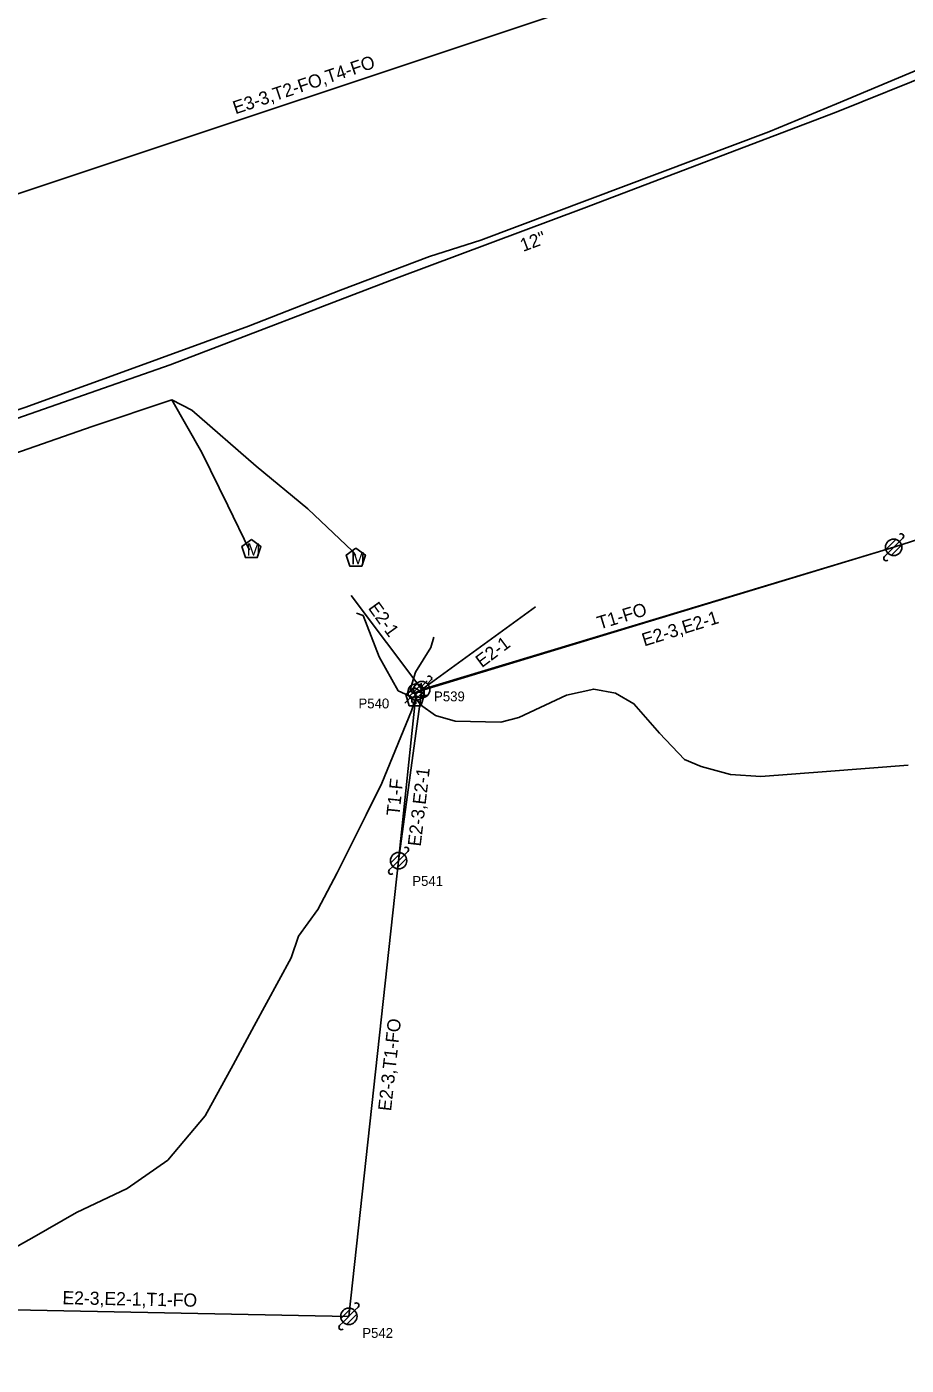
# Model space of a CAD drawing. Extents: x 1614474 to 1865144, y 1098877 to 1212550.
# Drawn here: x 1813359.1 to 1813627, y 1189614.1 to 1190021.4 of the extents above; entities that cross this region are included whole.
import ezdxf

# ---------------------------------------------------------------- set-up
doc = ezdxf.new("R2010")
doc.units = 0
for name, color, linetype in [('RD_EX_SU_H2O', 7, 'Continuous'), ('RD_EX_SU_Ovhd', 7, 'Continuous'), ('RD_EX_SU_Pole', 7, 'Continuous'), ('RD_EX_SU_Telecom', 7, 'Continuous'), ('RD_EX_SU_TX_H2O', 7, 'Continuous'), ('RD_EX_SU_TX_Pole', 7, 'Continuous')]:
    doc.layers.add(name, color=color, linetype=linetype)

# ---------------------------------------------------------------- blocks, each defined once
blk = doc.blocks.new('SUE_TPP')
at = {"layer": 'RD_EX_SU_Telecom'}
blk.add_lwpolyline([(0, 3), (-2.85, 0.93), (-1.76, -2.43), (1.76, -2.43), (2.85, 0.93)], close=True, dxfattribs=at)
blk.add_text('T', height=3.75, dxfattribs=at).set_placement((-1.25, -1.88))
blk = doc.blocks.new('SUE_WM')
at = {"layer": 'RD_EX_SU_H2O'}
blk.add_lwpolyline([(0, 3.05), (-2.9, 0.94), (-1.79, -2.47), (1.79, -2.47), (2.9, 0.94)], close=True, dxfattribs=at)
blk.add_text('M', height=3.75, dxfattribs=at).set_placement((-1.43, -1.88))
blk = doc.blocks.new('SUE_PTP')
at = {"layer": 'RD_EX_SU_Pole'}
for p, q in [((-2.48, -0.33), (0.33, 2.48)), ((-2.1, -1.36), (1.36, 2.1)), ((-1.4, -2.08), (2.08, 1.4)), ((-0.38, -2.47), (2.47, 0.38)), ((1.77, 1.77), (3.42, 3.42)), ((-3.42, -3.42), (-1.77, -1.77)), ((1.52, -1.99), (1.99, -1.52))]:
    blk.add_line(p, q, dxfattribs=at)
blk.add_circle((0, 0), 2.5, dxfattribs=at)

msp = doc.modelspace()

# ---------------------------------------------------------------- linework, layer by layer
at = {"layer": 'RD_EX_SU_H2O'}
for points in [[(1813049.93, 1189785.18), (1813062.98, 1189793.04), (1813077.41, 1189801.91), (1813100.8, 1189813.52), (1813124.24, 1189823.21), (1813173.48, 1189839.48), (1813207.95, 1189850.5), (1813242.12, 1189860.74), (1813307.93, 1189883.34), (1813347.93, 1189899.33), (1813402.79, 1189918.54), (1813471.7, 1189944.89), (1813528.83, 1189966.2), (1813605.69, 1189995.43), (1813667.12, 1190020.2)], [(1813076.17, 1189776.71), (1813070.48, 1189788.22), (1813083.19, 1189794.03), (1813114.42, 1189806.57), (1813134.39, 1189813.94), (1813156.92, 1189822.09), (1813179.27, 1189830.15), (1813208.26, 1189840.49), (1813244.46, 1189853.13), (1813287.8, 1189867.84), (1813318.33, 1189878.33), (1813350.77, 1189889.9), (1813379.04, 1189899.78), (1813403.28, 1189907.87), (1813412.45, 1189891.9), (1813420.34, 1189875.71), (1813427, 1189862.13)], [(1813403.28, 1189907.87), (1813409.4, 1189904.72), (1813429.03, 1189887.68), (1813444.72, 1189874.7), (1813458.39, 1189861.86), (1813459.22, 1189860.46)]]:
    msp.add_lwpolyline(points, dxfattribs=at)
at = {"layer": 'RD_EX_SU_Ovhd'}
for p, q in [((1813319.93, 1189958.41), (1813557.25, 1190037.52)), ((1813623.17, 1189863), (1813729.49, 1189897.64)), ((1813623.17, 1189863), (1813726.98, 1189897)), ((1813477.7, 1189818.95), (1813623.17, 1189863)), ((1813479.42, 1189819.69), (1813623.17, 1189863)), ((1813457.89, 1189848.34), (1813479.42, 1189819.69)), ((1813479.42, 1189819.69), (1813514.05, 1189844.91)), ((1813472.38, 1189767.62), (1813479.42, 1189819.69)), ((1813472.38, 1189767.62), (1813477.7, 1189818.95)), ((1813457.23, 1189628.94), (1813472.38, 1189767.62)), ((1813313.8, 1189631.73), (1813457.23, 1189628.94))]:
    msp.add_line(p, q, dxfattribs=at)
at = {"layer": 'RD_EX_SU_Pole'}
for p, q in [((1813620.76, 1189862.36), (1813623.82, 1189865.42)), ((1813621.41, 1189861.24), (1813624.94, 1189864.77)), ((1813622.53, 1189860.59), (1813625.59, 1189863.65)), ((1813624.94, 1189864.77), (1813626, 1189865.83)), ((1813620.34, 1189860.18), (1813621.41, 1189861.24)), ((1813481.18, 1189821.46), (1813482.24, 1189822.52)), ((1813476.59, 1189816.86), (1813477.65, 1189817.92)), ((1813469.97, 1189766.97), (1813473.03, 1189770.04)), ((1813470.62, 1189765.85), (1813474.15, 1189769.39)), ((1813474.15, 1189769.39), (1813475.21, 1189770.45)), ((1813469.56, 1189764.79), (1813470.62, 1189765.85)), ((1813471.74, 1189765.21), (1813474.8, 1189768.27)), ((1813454.81, 1189628.29), (1813457.88, 1189631.35)), ((1813455.46, 1189627.17), (1813459, 1189630.71)), ((1813459, 1189630.71), (1813460.06, 1189631.77)), ((1813454.4, 1189626.11), (1813455.46, 1189627.17)), ((1813456.58, 1189626.52), (1813459.64, 1189629.59))]:
    msp.add_line(p, q, dxfattribs=at)
for centre in [(1813623.17, 1189863), (1813479.42, 1189819.69), (1813472.38, 1189767.62), (1813457.23, 1189628.94)]:
    msp.add_circle(centre, 2.5, dxfattribs=at)
for centre, start, end in [((1813625.47, 1189866.36), 315, 135), ((1813620.88, 1189859.64), 135, 315), ((1813481.71, 1189823.05), 315, 135), ((1813477.12, 1189816.33), 135, 315), ((1813474.68, 1189770.98), 315, 135), ((1813470.09, 1189764.26), 135, 315), ((1813459.53, 1189632.3), 315, 135), ((1813454.93, 1189625.58), 135, 315)]:
    msp.add_arc(centre, 0.75, start, end, dxfattribs=at)
at = {"layer": 'RD_EX_SU_Telecom'}
for points in [[(1813481.84, 1189951.54), (1813497.41, 1189956.53), (1813585.12, 1189989.42), (1813605.76, 1189998.02), (1813630.95, 1190008.57)], [(1812986.98, 1189763.67), (1813005.44, 1189771.75), (1813024.19, 1189779.33), (1813053.31, 1189794.14), (1813073.59, 1189804.15), (1813101.03, 1189816.06), (1813126.47, 1189826.28), (1813144.04, 1189832.67), (1813167.98, 1189840.52), (1813203.88, 1189852.88), (1813226.05, 1189860.24), (1813250.43, 1189868.52), (1813290.34, 1189882.36), (1813332.67, 1189897.04), (1813358.52, 1189905.57), (1813386.31, 1189915.56), (1813426.66, 1189930.34), (1813454.68, 1189941.28), (1813481.84, 1189951.54)], [(1813459.57, 1189842.94), (1813461.58, 1189842.22), (1813466.47, 1189829.65), (1813472.27, 1189819.33), (1813476.93, 1189817.17)], [(1813476.97, 1189818.43), (1813475.95, 1189819.6), (1813477.55, 1189825.01), (1813482.2, 1189832.47), (1813483.12, 1189835.62)], [(1813477.62, 1189817.11), (1813479.05, 1189815.03), (1813483.64, 1189811.8), (1813489.65, 1189810.12), (1813503.52, 1189809.81), (1813509.02, 1189811.22), (1813523.55, 1189817.96), (1813531.82, 1189819.83), (1813538.49, 1189818.65), (1813544.05, 1189815.39), (1813551.84, 1189806.41), (1813559.42, 1189798.39), (1813564.52, 1189796.34), (1813573.51, 1189793.88), (1813582.72, 1189793.29), (1813602.71, 1189794.8), (1813627.54, 1189796.74)], [(1813255.57, 1189614.06), (1813263.68, 1189617.82), (1813281.32, 1189622.74), (1813302.06, 1189628.54), (1813321.29, 1189634.79), (1813337.62, 1189640.37), (1813352.54, 1189648.16), (1813361.42, 1189653.14), (1813374.32, 1189660.59), (1813389.71, 1189667.88), (1813402.08, 1189676.45), (1813413.44, 1189689.97), (1813422.05, 1189705.47), (1813428.42, 1189717.32), (1813439.68, 1189738.07), (1813441.87, 1189744.68), (1813447.8, 1189752.78), (1813453.72, 1189763.94), (1813462.54, 1189781.61), (1813467.31, 1189791.17), (1813476.35, 1189813.22), (1813477.46, 1189816.76)]]:
    msp.add_lwpolyline(points, dxfattribs=at)

# ---------------------------------------------------------------- block references
at = {"layer": 'RD_EX_SU_H2O'}
for p in [(1813427.54, 1189862.35), (1813459.36, 1189859.7)]:
    msp.add_blockref('SUE_WM', p, dxfattribs=at)
at = {"layer": 'RD_EX_SU_Telecom'}
for name, p in [('SUE_PTP', (1813477.7, 1189818.95)), ('SUE_TPP', (1813477.4, 1189817.23))]:
    msp.add_blockref(name, p, dxfattribs=at)

# ---------------------------------------------------------------- texts
at = {"layer": 'RD_EX_SU_Ovhd'}
for s, rotation, p in [('E3-3,T2-FO,T4-FO', 18.4353, (1813422.7, 1189994.77)), ('E2-1', 305.9302, (1813462.93, 1189844.51)), ('T1-FO', 16.848, (1813533.55, 1189837.95)), ('E2-3,E2-1', 17.3531, (1813547.21, 1189832.81)), ('E2-1', 36.8685, (1813497.72, 1189826.2)), ('E2-3,E2-1', 83.3067, (1813479.11, 1189771.85)), ('T1-F', 84.087, (1813472.63, 1189781.16)), ('E2-3,T1-FO', 83.7637, (1813470.08, 1189691.29)), ('E2-3,E2-1,T1-FO', 358.8851, (1813369.97, 1189632.64))]:
    msp.add_text(s, height=4, rotation=rotation, dxfattribs=at).set_placement(p)
at = {"layer": 'RD_EX_SU_Pole'}
msp.add_text('L', height=4, dxfattribs=at).set_placement((1813478.55, 1189817.69))
at = {"layer": 'RD_EX_SU_TX_H2O'}
msp.add_text('12"', height=4, rotation=20.4584, dxfattribs=at).set_placement((1813510.29, 1189952.88))
at = {"layer": 'RD_EX_SU_TX_Pole'}
for s, p in [('P539', (1813483.18, 1189816.12)), ('P540', (1813460.16, 1189813.98)), ('P541', (1813476.55, 1189759.94)), ('P542', (1813461.32, 1189622.38))]:
    msp.add_text(s, height=3, dxfattribs=at).set_placement(p)

doc.saveas('drawing.dxf')
